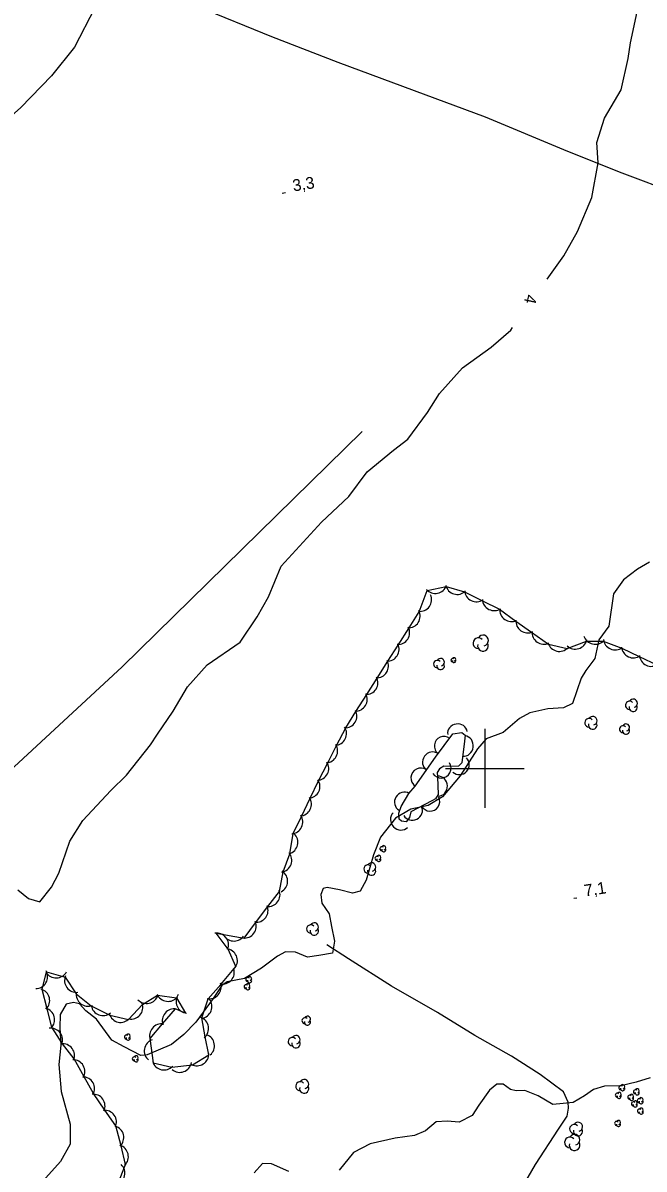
# Model space of a CAD drawing. Extents: x 643342 to 646936, y 5873857 to 5876103.
# Drawn here: x 645282.9 to 645440.4, y 5874698.4 to 5874989 of the extents above; entities that cross this region are included whole.
import ezdxf

# ---------------------------------------------------------------- set-up
doc = ezdxf.new("R2010")
doc.units = 0
for name, color, linetype in [('Niveau 2', 7, 'Continuous'), ('Niveau 22', 7, 'Continuous'), ('Niveau 3', 7, 'Continuous'), ('Niveau 4', 7, 'Continuous'), ('Niveau 44', 7, 'Continuous'), ('Niveau 61', 7, 'Continuous')]:
    doc.layers.add(name, color=color, linetype=linetype)

msp = doc.modelspace()

# ---------------------------------------------------------------- linework, layer by layer
at = {"layer": 'Niveau 2'}
for points in [[(645415.83, 5874924.08), (645420, 5874929.98), (645423.47, 5874936.13), (645427.12, 5874944.77), (645428.77, 5874953.53), (645428.43, 5874958.73), (645430.37, 5874964.84), (645434.59, 5874972.04), (645436.35, 5874979.98), (645436.97, 5874983.93), (645438.84, 5874993.01)], [(645281.59, 5874769.17), (645284.32, 5874767.03), (645287.2, 5874766.15), (645290.12, 5874769.84), (645292, 5874773.39), (645294.74, 5874781.51), (645298.03, 5874786.81), (645305.16, 5874794.38), (645309.12, 5874798.31), (645315.19, 5874805.93), (645317, 5874808.65), (645321.01, 5874814.53), (645324.59, 5874820.69), (645329.63, 5874826.22), (645337.93, 5874831.97), (645342.31, 5874838.41), (645345.15, 5874843.45), (645348.38, 5874851.24), (645358.55, 5874862.44), (645365.51, 5874868.93), (645370.15, 5874875.15), (645376.82, 5874880.67), (645380.5, 5874883.51), (645385.45, 5874890.22), (645388.54, 5874895.04), (645394.32, 5874901.57), (645401.6, 5874906.77), (645406.59, 5874911.12), (645407.04, 5874911.75)], [(645150.74, 5874674.21), (645189.93, 5874712.68), (645233.73, 5874757.01), (645308.06, 5874825.78), (645368.92, 5874885.42)], [(645441.78, 5874852.28), (645438.74, 5874850.49), (645435.18, 5874847.84), (645432.66, 5874844.26), (645431.45, 5874836.08), (645428.93, 5874832.55), (645427.89, 5874827.88), (645425.64, 5874824.84), (645424.42, 5874822.87), (645422.27, 5874816.47), (645419.95, 5874815.38), (645415.99, 5874815.12), (645411.38, 5874814.06), (645408.78, 5874812.65), (645404.69, 5874809.08), (645400.35, 5874807.44), (645398.12, 5874804.93), (645393.77, 5874798.1), (645389.27, 5874792.78), (645385.62, 5874790.54), (645381.23, 5874789.61), (645377.34, 5874787.35), (645373.51, 5874782.55), (645371.81, 5874778.07), (645369.9, 5874771.68), (645368.38, 5874768.87), (645366.43, 5874768.33), (645363.16, 5874769.18), (645360.01, 5874769.8), (645359.04, 5874769.5), (645358.43, 5874768.04), (645358.7, 5874765.82), (645360.52, 5874763.1), (645361.08, 5874759.89), (645361.85, 5874756.16), (645361.35, 5874753.11)], [(645361.35, 5874753.11), (645357.94, 5874752.54), (645355.04, 5874752.11), (645352.03, 5874753.39), (645349.45, 5874753.46), (645347.42, 5874752.33), (645343.4, 5874749.35), (645339.07, 5874746.7), (645334.68, 5874745.83), (645333.33, 5874744.91), (645331.09, 5874741.63), (645326.69, 5874735.62), (645323.67, 5874732.53), (645320.56, 5874729.96), (645314.41, 5874727.32), (645312.78, 5874727.21), (645308.53, 5874729.41), (645305.44, 5874731.04), (645301.56, 5874736.4), (645298.84, 5874738.53), (645297.26, 5874740.26), (645295.71, 5874740.63), (645293.87, 5874740.22), (645292.28, 5874737.57), (645292.22, 5874734.2), (645292.51, 5874729.79), (645291.96, 5874724.91), (645292.54, 5874718.03), (645294.85, 5874709.79), (645294.83, 5874704.71), (645292.43, 5874700.3), (645287.96, 5874695.29)], [(645441.91, 5874721.48), (645438.36, 5874720.43), (645434.46, 5874719.52), (645430.33, 5874719.37), (645427.58, 5874718.6), (645425.24, 5874716.98), (645422.43, 5874715.26), (645419.88, 5874714.98), (645417.22, 5874714.74), (645413.51, 5874716.97), (645410.15, 5874718.35), (645407.92, 5874718.2), (645406.53, 5874718.52), (645404.68, 5874719.9), (645403.05, 5874719.88), (645401.19, 5874718.41), (645398.5, 5874714.58), (645396.75, 5874711.96), (645393.47, 5874710.3), (645390.42, 5874710.52), (645387.69, 5874710.39), (645384.92, 5874708.09), (645382.19, 5874706.91), (645377.28, 5874706.18), (645370.95, 5874704.76), (645366.66, 5874702.6), (645363.1, 5874698.12)], [(645350.33, 5874697.75), (645345.94, 5874699.7), (645343.65, 5874699.79), (645341.53, 5874697.41)]]:
    msp.add_lwpolyline(points, dxfattribs=at)
at = {"layer": 'Niveau 22'}
for points in [[(645603.81, 5874883.86), (645574.47, 5874897.74), (645517.58, 5874918.6), (645500.14, 5874925.89), (645484.76, 5874931.99), (645475.39, 5874936.46), (645463.73, 5874942.3), (645460.49, 5874943.58), (645456.16, 5874943.99), (645448.77, 5874945.7), (645434.83, 5874950.95), (645421.06, 5874956.4), (645400.15, 5874965.16), (645382.17, 5874971.82), (645362.77, 5874978.95), (645345.98, 5874985.51), (645327.34, 5874993.09), (645292.44, 5875007.54), (645277.84, 5875013.59), (645259.27, 5875020.3), (645243.98, 5875025.32), (645222.92, 5875033.97), (645202.37, 5875044.62)], [(645398.58, 5874677.3), (645402.88, 5874682.87), (645407.31, 5874689.87), (645412.85, 5874699.53), (645418.68, 5874708.51), (645420.91, 5874711.83), (645421.24, 5874713.86), (645421.14, 5874715.38), (645419.92, 5874718.01), (645414.03, 5874722.34), (645406.72, 5874727.04), (645397.5, 5874732.22), (645388.01, 5874738.08), (645376.34, 5874744.76), (645365.47, 5874751.72), (645359.97, 5874755.26)]]:
    msp.add_lwpolyline(points, dxfattribs=at)
at = {"layer": 'Niveau 3'}
for p, q in [((645348.63, 5874945.86), (645349.42, 5874945.99)), ((645422.57, 5874767.06), (645423.36, 5874767.19))]:
    msp.add_line(p, q, dxfattribs=at)
at = {"layer": 'Niveau 4'}
msp.add_lwpolyline([(645301.14, 5874992.82), (645295.93, 5874982.89), (645290.14, 5874975.61), (645282.31, 5874967.54), (645271.78, 5874958.15), (645258.44, 5874947.3), (645250.69, 5874940.89), (645244.69, 5874937.12), (645222.84, 5874922.84), (645213.2, 5874916.35), (645202.34, 5874907.73), (645191.75, 5874899.97), (645181.06, 5874891.96), (645175.18, 5874888.07), (645172.07, 5874887.3), (645168.4, 5874886.23), (645164.79, 5874884.58), (645161.72, 5874880.73), (645158.19, 5874874.12), (645151.58, 5874861.06), (645143.89, 5874846.83)], dxfattribs=at)
at = {"layer": 'Niveau 44'}
for points in [[(645300.79, 5874717.57), (645298.37, 5874721.77), (645295.85, 5874726.31), (645292.89, 5874730.16), (645290.23, 5874734.35), (645289.02, 5874739.05), (645287.77, 5874743.89), (645288.88, 5874748.36), (645293.56, 5874747.07), (645296.38, 5874742.8), (645300.2, 5874739.8), (645304.9, 5874737.37), (645309.64, 5874736.34), (645313.21, 5874740.08), (645317.03, 5874742.48), (645321.84, 5874741.83), (645324.06, 5874737.96), (645321.44, 5874738.99), (645318.2, 5874735.18), (645315.06, 5874731.48), (645315.89, 5874725.32), (645320.62, 5874724.26), (645325.9, 5874724.79), (645330, 5874727.38), (645329.08, 5874731.92), (645328.27, 5874736.7), (645329.86, 5874741.56), (645333.09, 5874745.19), (645336.87, 5874749.74), (645334.88, 5874754.17), (645331.86, 5874758.21), (645338.99, 5874756.96), (645341.88, 5874760.86), (645345, 5874764.95), (645347.94, 5874768.81), (645348.87, 5874773.79), (645350.54, 5874778.34), (645351.38, 5874783.45), (645353.49, 5874787.82), (645355.72, 5874792.46), (645357.83, 5874796.83), (645360.15, 5874801.42), (645362.35, 5874805.75), (645364.77, 5874810.26), (645367.33, 5874814.38), (645370.06, 5874818.74), (645372.67, 5874822.83), (645375.44, 5874827.17), (645378.04, 5874831.27), (645380.8, 5874835.61), (645383.39, 5874839.72), (645385.4, 5874845.13), (645390.17, 5874846.08), (645394.83, 5874844.73), (645399.41, 5874842.49), (645403.75, 5874840.33), (645407.87, 5874837.29), (645411.84, 5874834.5), (645416.14, 5874831.49), (645420.86, 5874830.37), (645425.77, 5874832.25), (645429.97, 5874832.22), (645434.73, 5874830.45), (645439.11, 5874828.37), (645443.76, 5874826.17)], [(645382.36, 5874795.51), (645387.48, 5874802.87), (645391.85, 5874808.72), (645394.16, 5874809.11), (645395, 5874808.4), (645394.84, 5874806.92), (645394.14, 5874801.4), (645393.34, 5874800.55), (645391.49, 5874800.49), (645389.64, 5874800.52), (645388.52, 5874799.84), (645387.92, 5874798.91), (645388.01, 5874797.85), (645388.2, 5874793.37), (645387.52, 5874792.24), (645386.59, 5874791.77), (645381.27, 5874788.97), (645380.9, 5874787.57), (645380.02, 5874786.42), (645378.84, 5874786.61), (645378.3, 5874787.15), (645378.18, 5874788.61), (645378.81, 5874790.32), (645380.77, 5874793.61), (645382.36, 5874795.51)], [(645306.94, 5874694.57), (645308.88, 5874699.58), (645307.76, 5874704.3), (645306.44, 5874709.35), (645303.62, 5874713.3), (645300.79, 5874717.57)]]:
    msp.add_lwpolyline(points, dxfattribs=at)
for centre, radius, start, end in [((645387.42, 5874847.34), 3, 221.5267, 341.5047), ((645387.42, 5874847.34), 3, 221.5267, 341.5047), ((645387.42, 5874847.34), 3, 221.5267, 341.5047), ((645392.99, 5874847.1), 3, 193.848, 313.8259), ((645392.99, 5874847.1), 3, 193.848, 313.8259), ((645392.99, 5874847.1), 3, 193.848, 313.8259), ((645383.51, 5874842.8), 3, 263.8061, 23.7841), ((645383.51, 5874842.8), 3, 263.8061, 23.7841), ((645383.51, 5874842.8), 3, 263.8061, 23.7841), ((645397.89, 5874845.22), 3, 183.5164, 303.4944), ((645397.89, 5874845.22), 3, 183.5164, 303.4944), ((645397.89, 5874845.22), 3, 183.5164, 303.4944), ((645402.37, 5874842.99), 3, 183.5164, 303.4944), ((645402.37, 5874842.99), 3, 183.5164, 303.4944), ((645402.37, 5874842.99), 3, 183.5164, 303.4944), ((645380.6, 5874838.61), 3, 267.6564, 27.6343), ((645380.6, 5874838.61), 3, 267.6564, 27.6343), ((645380.6, 5874838.61), 3, 267.6564, 27.6343), ((645406.77, 5874840.21), 3, 174.9656, 294.9436), ((645406.77, 5874840.21), 3, 174.9656, 294.9436), ((645406.77, 5874840.21), 3, 174.9656, 294.9436), ((645410.87, 5874837.34), 3, 174.9656, 294.9436), ((645410.87, 5874837.34), 3, 174.9656, 294.9436), ((645410.87, 5874837.34), 3, 174.9656, 294.9436), ((645377.93, 5874834.39), 3, 267.6564, 27.6343), ((645377.93, 5874834.39), 3, 267.6564, 27.6343), ((645377.93, 5874834.39), 3, 267.6564, 27.6343), ((645414.96, 5874834.47), 3, 174.9656, 294.9436), ((645414.96, 5874834.47), 3, 174.9656, 294.9436), ((645414.96, 5874834.47), 3, 174.9656, 294.9436), ((645375.25, 5874830.16), 3, 267.6564, 27.6343), ((645375.25, 5874830.16), 3, 267.6564, 27.6343), ((645375.25, 5874830.16), 3, 267.6564, 27.6343), ((645398.36, 5874831.75), 1.36, 44.1154, 269.804), ((645399.53, 5874831.07), 1.36, 166.9369, 29.6212), ((645399.53, 5874832.43), 1.36, 282.2692, 149.7263), ((645418.91, 5874832.65), 3, 196.6699, 316.6478), ((645418.91, 5874832.65), 3, 196.6699, 316.6478), ((645418.91, 5874832.65), 3, 196.6699, 316.6478), ((645422.93, 5874833.23), 3, 226.9641, 346.942), ((645422.93, 5874833.23), 3, 226.9641, 346.942), ((645422.93, 5874833.23), 3, 226.9641, 346.942), ((645427.98, 5874834.46), 3, 197.5872, 317.5651), ((645427.98, 5874834.46), 3, 197.5872, 317.5651), ((645427.98, 5874834.46), 3, 197.5872, 317.5651), ((645433.05, 5874833.03), 3, 186.4269, 306.4048), ((645433.05, 5874833.03), 3, 186.4269, 306.4048), ((645433.05, 5874833.03), 3, 186.4269, 306.4048), ((645437.68, 5874831.01), 3, 184.6385, 304.6165), ((645437.68, 5874831.01), 3, 184.6385, 304.6165), ((645437.68, 5874831.01), 3, 184.6385, 304.6165), ((645442.19, 5874828.86), 3, 184.6385, 304.6165), ((645442.19, 5874828.86), 3, 184.6385, 304.6165), ((645442.19, 5874828.86), 3, 184.6385, 304.6165), ((645372.57, 5874825.95), 3, 267.4959, 27.4739), ((645372.57, 5874825.95), 3, 267.4959, 27.4739), ((645372.57, 5874825.95), 3, 267.4959, 27.4739), ((645387.97, 5874826.44), 0.952, 44.1154, 269.804), ((645388.79, 5874825.97), 0.952, 166.9369, 29.6212), ((645388.79, 5874826.92), 0.952, 282.2692, 149.7263), ((645391.82, 5874827.43), 0.429, 44.1154, 269.804), ((645392.19, 5874827.22), 0.429, 166.9369, 29.6212), ((645392.19, 5874827.64), 0.429, 282.2692, 149.7263), ((645369.88, 5874821.73), 3, 267.4959, 27.4739), ((645369.88, 5874821.73), 3, 267.4959, 27.4739), ((645369.88, 5874821.73), 3, 267.4959, 27.4739), ((645367.19, 5874817.5), 3, 268.1702, 28.1482), ((645367.19, 5874817.5), 3, 268.1702, 28.1482), ((645367.19, 5874817.5), 3, 268.1702, 28.1482), ((645436.72, 5874815.98), 1.05, 44.1154, 269.804), ((645437.62, 5874816.51), 1.05, 282.2692, 149.7263), ((645364.55, 5874813.25), 3, 268.1702, 28.1482), ((645364.55, 5874813.25), 3, 268.1702, 28.1482), ((645364.55, 5874813.25), 3, 268.1702, 28.1482), ((645437.62, 5874815.46), 1.05, 166.9369, 29.6212), ((645426.43, 5874811.54), 1.09, 44.1154, 269.804), ((645427.37, 5874811), 1.09, 166.9369, 29.6212), ((645427.37, 5874812.09), 1.09, 282.2692, 149.7263), ((645435.04, 5874809.94), 0.88, 44.1154, 269.804), ((645435.8, 5874810.38), 0.88, 282.2692, 149.7263), ((645361.94, 5874808.84), 3, 273.0656, 33.0436), ((645361.94, 5874808.84), 3, 273.0656, 33.0436), ((645361.94, 5874808.84), 3, 273.0656, 33.0436), ((645435.8, 5874809.5), 0.88, 166.9369, 29.6212), ((645359.67, 5874804.38), 3, 273.0656, 33.0436), ((645359.67, 5874804.38), 3, 273.0656, 33.0436), ((645359.67, 5874804.38), 3, 273.0656, 33.0436), ((645357.41, 5874799.93), 3, 273.0656, 33.0436), ((645357.41, 5874799.93), 3, 273.0656, 33.0436), ((645357.41, 5874799.93), 3, 273.0656, 33.0436), ((645355.19, 5874795.41), 3, 274.2807, 34.2586), ((645355.19, 5874795.41), 3, 274.2807, 34.2586), ((645355.19, 5874795.41), 3, 274.2807, 34.2586), ((645353.02, 5874790.91), 3, 274.2807, 34.2586), ((645353.02, 5874790.91), 3, 274.2807, 34.2586), ((645353.02, 5874790.91), 3, 274.2807, 34.2586), ((645350.85, 5874786.4), 3, 274.2807, 34.2586), ((645350.85, 5874786.4), 3, 274.2807, 34.2586), ((645350.85, 5874786.4), 3, 274.2807, 34.2586), ((645349.59, 5874781.22), 3, 286.9389, 46.9169), ((645349.59, 5874781.22), 3, 286.9389, 46.9169), ((645349.59, 5874781.22), 3, 286.9389, 46.9169), ((645373.92, 5874779.61), 0.523, 44.1154, 269.804), ((645374.37, 5874779.35), 0.523, 166.9369, 29.6212), ((645374.37, 5874779.87), 0.523, 282.2692, 149.7263), ((645348.05, 5874776.67), 3, 279.823, 39.8009), ((645348.05, 5874776.67), 3, 279.823, 39.8009), ((645348.05, 5874776.67), 3, 279.823, 39.8009), ((645371.28, 5874774.99), 1.05, 282.2692, 149.7263), ((645372.67, 5874777.16), 0.523, 44.1154, 269.804), ((645373.12, 5874776.9), 0.523, 166.9369, 29.6212), ((645373.12, 5874777.42), 0.523, 282.2692, 149.7263), ((645347, 5874771.38), 3, 297.1694, 57.1474), ((645347, 5874771.38), 3, 297.1694, 57.1474), ((645347, 5874771.38), 3, 297.1694, 57.1474), ((645370.38, 5874774.46), 1.05, 44.1154, 269.804), ((645371.28, 5874773.94), 1.05, 166.9369, 29.6212), ((645345.07, 5874767.95), 3, 262.7475, 22.7255), ((645345.07, 5874767.95), 3, 262.7475, 22.7255), ((645345.07, 5874767.95), 3, 262.7475, 22.7255), ((645342.04, 5874763.97), 3, 262.7475, 22.7255), ((645342.04, 5874763.97), 3, 262.7475, 22.7255), ((645342.04, 5874763.97), 3, 262.7475, 22.7255), ((645339.02, 5874759.96), 3, 263.4418, 23.4197), ((645339.02, 5874759.96), 3, 263.4418, 23.4197), ((645339.02, 5874759.96), 3, 263.4418, 23.4197), ((645355.86, 5874759.26), 1.05, 44.1154, 269.804), ((645356.76, 5874758.74), 1.05, 166.9369, 29.6212), ((645356.76, 5874759.79), 1.05, 282.2692, 149.7263), ((645332.01, 5874755.22), 3, 338.7736, 98.7515), ((645332.01, 5874755.22), 3, 338.7736, 98.7515), ((645332.01, 5874755.22), 3, 338.7736, 98.7515), ((645336.37, 5874759.21), 3, 203.5243, 323.5022), ((645336.37, 5874759.21), 3, 203.5243, 323.5022), ((645336.37, 5874759.21), 3, 203.5243, 323.5022), ((645334.26, 5874751.23), 3, 324.2038, 84.1817), ((645334.26, 5874751.23), 3, 324.2038, 84.1817), ((645334.26, 5874751.23), 3, 324.2038, 84.1817), ((645286.13, 5874747.16), 3, 269.5308, 29.5087), ((645286.13, 5874747.16), 3, 269.5308, 29.5087), ((645286.13, 5874747.16), 3, 269.5308, 29.5087), ((645291.31, 5874749.85), 3, 211.3344, 331.3123), ((645291.31, 5874749.85), 3, 211.3344, 331.3123), ((645291.31, 5874749.85), 3, 211.3344, 331.3123), ((645296.43, 5874746.19), 3, 156.9036, 276.8815), ((645296.43, 5874746.19), 3, 156.9036, 276.8815), ((645296.43, 5874746.19), 3, 156.9036, 276.8815), ((645333.48, 5874748.28), 3, 258.3486, 18.3265), ((645333.48, 5874748.28), 3, 258.3486, 18.3265), ((645333.48, 5874748.28), 3, 258.3486, 18.3265), ((645339.91, 5874746.42), 0.523, 44.1154, 269.804), ((645340.36, 5874746.68), 0.523, 282.2692, 149.7263), ((645286.67, 5874741.1), 3, 314.4228, 74.4007), ((645286.67, 5874741.1), 3, 314.4228, 74.4007), ((645286.67, 5874741.1), 3, 314.4228, 74.4007), ((645330.16, 5874744.55), 3, 258.3486, 18.3265), ((645330.16, 5874744.55), 3, 258.3486, 18.3265), ((645330.16, 5874744.55), 3, 258.3486, 18.3265), ((645339.48, 5874744.62), 0.523, 44.1154, 269.804), ((645339.93, 5874744.36), 0.523, 166.9369, 29.6212), ((645339.93, 5874744.88), 0.523, 282.2692, 149.7263), ((645340.36, 5874746.16), 0.523, 166.9369, 29.6212), ((645299.38, 5874742.68), 3, 171.7847, 291.7626), ((645299.38, 5874742.68), 3, 171.7847, 291.7626), ((645299.38, 5874742.68), 3, 171.7847, 291.7626), ((645314.24, 5874743.37), 3, 222.5683, 342.5462), ((645314.24, 5874743.37), 3, 222.5683, 342.5462), ((645314.24, 5874743.37), 3, 222.5683, 342.5462), ((645319.67, 5874743.9), 3, 202.3429, 322.3208), ((645319.67, 5874743.9), 3, 202.3429, 322.3208), ((645319.67, 5874743.9), 3, 202.3429, 322.3208), ((645324.69, 5874740.89), 3, 143.8864, 263.8643), ((645324.69, 5874740.89), 3, 143.8864, 263.8643), ((645324.69, 5874740.89), 3, 143.8864, 263.8643), ((645327.81, 5874739.6), 3, 278.1445, 38.1225), ((645327.81, 5874739.6), 3, 278.1445, 38.1225), ((645327.81, 5874739.6), 3, 278.1445, 38.1225), ((645287.91, 5874736.26), 3, 314.4228, 74.4007), ((645287.91, 5874736.26), 3, 314.4228, 74.4007), ((645287.91, 5874736.26), 3, 314.4228, 74.4007), ((645303.18, 5874740.29), 3, 189.2185, 309.1965), ((645303.18, 5874740.29), 3, 189.2185, 309.1965), ((645303.18, 5874740.29), 3, 189.2185, 309.1965), ((645310.29, 5874739.4), 3, 259.0386, 19.0165), ((645310.29, 5874739.4), 3, 259.0386, 19.0165), ((645310.29, 5874739.4), 3, 259.0386, 19.0165), ((645321.21, 5874736), 3, 79.6841, 199.662), ((645321.21, 5874736), 3, 79.6841, 199.662), ((645321.21, 5874736), 3, 79.6841, 199.662), ((645307.65, 5874738.58), 3, 197.6811, 317.659), ((645307.65, 5874738.58), 3, 197.6811, 317.659), ((645307.65, 5874738.58), 3, 197.6811, 317.659), ((645317.98, 5874732.19), 3, 79.6841, 199.662), ((645317.98, 5874732.19), 3, 79.6841, 199.662), ((645317.98, 5874732.19), 3, 79.6841, 199.662), ((645326.94, 5874734.02), 3, 309.683, 69.6609), ((645326.94, 5874734.02), 3, 309.683, 69.6609), ((645326.94, 5874734.02), 3, 309.683, 69.6609), ((645354.38, 5874736.02), 0.757, 44.1154, 269.804), ((645355.03, 5874735.64), 0.757, 166.9369, 29.6212), ((645355.03, 5874736.4), 0.757, 282.2692, 149.7263), ((645289.93, 5874731.13), 3, 337.5162, 97.4941), ((645289.93, 5874731.13), 3, 337.5162, 97.4941), ((645289.93, 5874731.13), 3, 337.5162, 97.4941), ((645309.11, 5874731.85), 0.523, 44.1154, 269.804), ((645309.56, 5874732.11), 0.523, 282.2692, 149.7263), ((645328.45, 5874729.64), 3, 309.5524, 69.5303), ((645328.45, 5874729.64), 3, 309.5524, 69.5303), ((645328.45, 5874729.64), 3, 309.5524, 69.5303), ((645352.1, 5874731.22), 1.06, 282.2692, 149.7263), ((645292.97, 5874727.16), 3, 337.5162, 97.4941), ((645292.97, 5874727.16), 3, 337.5162, 97.4941), ((645292.97, 5874727.16), 3, 337.5162, 97.4941), ((645309.56, 5874731.59), 0.523, 166.9369, 29.6212), ((645316.64, 5874728.34), 3, 109.9104, 229.8884), ((645316.64, 5874728.34), 3, 109.9104, 229.8884), ((645316.64, 5874728.34), 3, 109.9104, 229.8884), ((645351.19, 5874730.69), 1.06, 44.1154, 269.804), ((645352.1, 5874730.16), 1.06, 166.9369, 29.6212), ((645311.13, 5874726.34), 0.523, 44.1154, 269.804), ((645311.58, 5874726.6), 0.523, 282.2692, 149.7263), ((645327.01, 5874727.58), 3, 242.2808, 2.2587), ((645327.01, 5874727.58), 3, 242.2808, 2.2587), ((645327.01, 5874727.58), 3, 242.2808, 2.2587), ((645295.56, 5874723.12), 3, 329.9657, 89.9437), ((645295.56, 5874723.12), 3, 329.9657, 89.9437), ((645295.56, 5874723.12), 3, 329.9657, 89.9437), ((645311.58, 5874726.08), 0.523, 166.9369, 29.6212), ((645318.64, 5874726.51), 3, 197.3175, 317.2955), ((645318.64, 5874726.51), 3, 197.3175, 317.2955), ((645318.64, 5874726.51), 3, 197.3175, 317.2955), ((645322.64, 5874725.91), 3, 230.0079, 349.9858), ((645322.64, 5874725.91), 3, 230.0079, 349.9858), ((645322.64, 5874725.91), 3, 230.0079, 349.9858), ((645298.05, 5874718.79), 3, 329.9657, 89.9437), ((645298.05, 5874718.79), 3, 329.9657, 89.9437), ((645298.05, 5874718.79), 3, 329.9657, 89.9437), ((645354.19, 5874719.95), 1.16, 282.2692, 149.7263), ((645353.2, 5874719.37), 1.16, 44.1154, 269.804), ((645354.19, 5874718.79), 1.16, 166.9369, 29.6212), ((645434.05, 5874717.34), 0.523, 282.2692, 149.7263), ((645434.5, 5874719.01), 0.523, 44.1154, 269.804), ((645434.95, 5874718.75), 0.523, 166.9369, 29.6212), ((645434.95, 5874719.27), 0.523, 282.2692, 149.7263), ((645438.2, 5874717.97), 0.523, 44.1154, 269.804), ((645438.65, 5874717.71), 0.523, 166.9369, 29.6212), ((645438.65, 5874718.23), 0.523, 282.2692, 149.7263), ((645300.69, 5874714.37), 3, 335.5328, 95.5108), ((645300.69, 5874714.37), 3, 335.5328, 95.5108), ((645300.69, 5874714.37), 3, 335.5328, 95.5108), ((645433.6, 5874717.08), 0.523, 44.1154, 269.804), ((645434.05, 5874716.82), 0.523, 166.9369, 29.6212), ((645436.76, 5874716.57), 0.523, 44.1154, 269.804), ((645437.21, 5874716.31), 0.523, 166.9369, 29.6212), ((645437.21, 5874716.83), 0.523, 282.2692, 149.7263), ((645437.69, 5874714.9), 0.523, 44.1154, 269.804), ((645438.14, 5874714.64), 0.523, 166.9369, 29.6212), ((645438.14, 5874715.16), 0.523, 282.2692, 149.7263), ((645439.17, 5874715.71), 0.523, 44.1154, 269.804), ((645439.62, 5874715.45), 0.523, 166.9369, 29.6212), ((645439.62, 5874715.97), 0.523, 282.2692, 149.7263), ((645303.59, 5874710.3), 3, 335.5328, 95.5108), ((645303.59, 5874710.3), 3, 335.5328, 95.5108), ((645303.59, 5874710.3), 3, 335.5328, 95.5108), ((645439.21, 5874713.08), 0.523, 44.1154, 269.804), ((645439.66, 5874712.82), 0.523, 166.9369, 29.6212), ((645439.66, 5874713.34), 0.523, 282.2692, 149.7263), ((645305.45, 5874706.39), 3, 313.3681, 73.3461), ((645305.45, 5874706.39), 3, 313.3681, 73.3461), ((645305.45, 5874706.39), 3, 313.3681, 73.3461), ((645422.65, 5874708.54), 1.15, 44.1154, 269.804), ((645423.64, 5874709.11), 1.15, 282.2692, 149.7263), ((645433.43, 5874709.95), 0.523, 44.1154, 269.804), ((645433.88, 5874709.69), 0.523, 166.9369, 29.6212), ((645433.88, 5874710.21), 0.523, 282.2692, 149.7263), ((645421.58, 5874705.14), 1.35, 44.1154, 269.804), ((645422.75, 5874705.82), 1.35, 282.2692, 149.7263), ((645423.64, 5874707.96), 1.15, 166.9369, 29.6212), ((645306.61, 5874701.53), 3, 313.3681, 73.3461), ((645306.61, 5874701.53), 3, 313.3681, 73.3461), ((645306.61, 5874701.53), 3, 313.3681, 73.3461), ((645422.75, 5874704.46), 1.35, 166.9369, 29.6212), ((645305.73, 5874697.31), 3, 287.648, 47.626), ((645305.73, 5874697.31), 3, 287.648, 47.626), ((645305.73, 5874697.31), 3, 287.648, 47.626)]:
    msp.add_arc(centre, radius, start, end, dxfattribs=at)
for centre, major_axis, ratio, start_param, end_param in [((645393.06, 5874808.96), (-2.47, -0.37), 0.919919, 3.141593, 6.283185), ((645389.61, 5874805.66), (-1.93, 1.48), 0.997449, 4.712389, 7.853982), ((645394.67, 5874805.68), (0.32, 2.58), 0.925819, 3.141593, 6.283185), ((645386.67, 5874801.65), (-1.47, -2.08), 0.952628, 3.141593, 6.283185), ((645393.62, 5874800.86), (1.7, 1.8), 0.970147, 3.141593, 6.283185), ((645383.76, 5874797.59), (-2.08, 1.38), 0.99999, 4.712389, 7.853982), ((645388.94, 5874800.04), (1.35, -2.1), 0.99999, 4.712389, 7.853982), ((645388.08, 5874795.48), (-0.08, 2.55), 0.952628, 3.141593, 6.283185), ((645379.53, 5874791.5), (-1.27, -2.13), 0.970147, 3.141593, 6.283185), ((645386.14, 5874791.57), (1.11, -2.16), 0.997449, 4.712389, 7.853982), ((645378.59, 5874786.87), (1.83, -1.85), 0.925819, 3.141593, 6.283185), ((645381.73, 5874789.17), (2.23, 1.12), 0.919919, 3.141593, 6.283185)]:
    msp.add_ellipse(centre, major_axis=major_axis, ratio=ratio, start_param=start_param, end_param=end_param, dxfattribs=at)
at = {"layer": 'Niveau 61'}
for points in [[(645400, 5874810), (645400, 5874800), (645400, 5874790)], [(645390, 5874800), (645400, 5874800), (645410, 5874800)]]:
    msp.add_lwpolyline(points, dxfattribs=at)

# ---------------------------------------------------------------- texts
at = {"layer": 'Niveau 2'}
msp.add_text('4', height=3, rotation=257.8346, dxfattribs=at).set_placement((645410.36, 5874920.34))
at = {"layer": 'Niveau 3'}
for s, p in [('3,3  ', (645351.48, 5874946.27)), ('7,1  ', (645425.42, 5874767.47))]:
    msp.add_text(s, height=3, rotation=8.941, dxfattribs=at).set_placement(p)

doc.saveas('drawing.dxf')
